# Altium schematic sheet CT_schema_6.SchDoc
size 371 x 245 mm
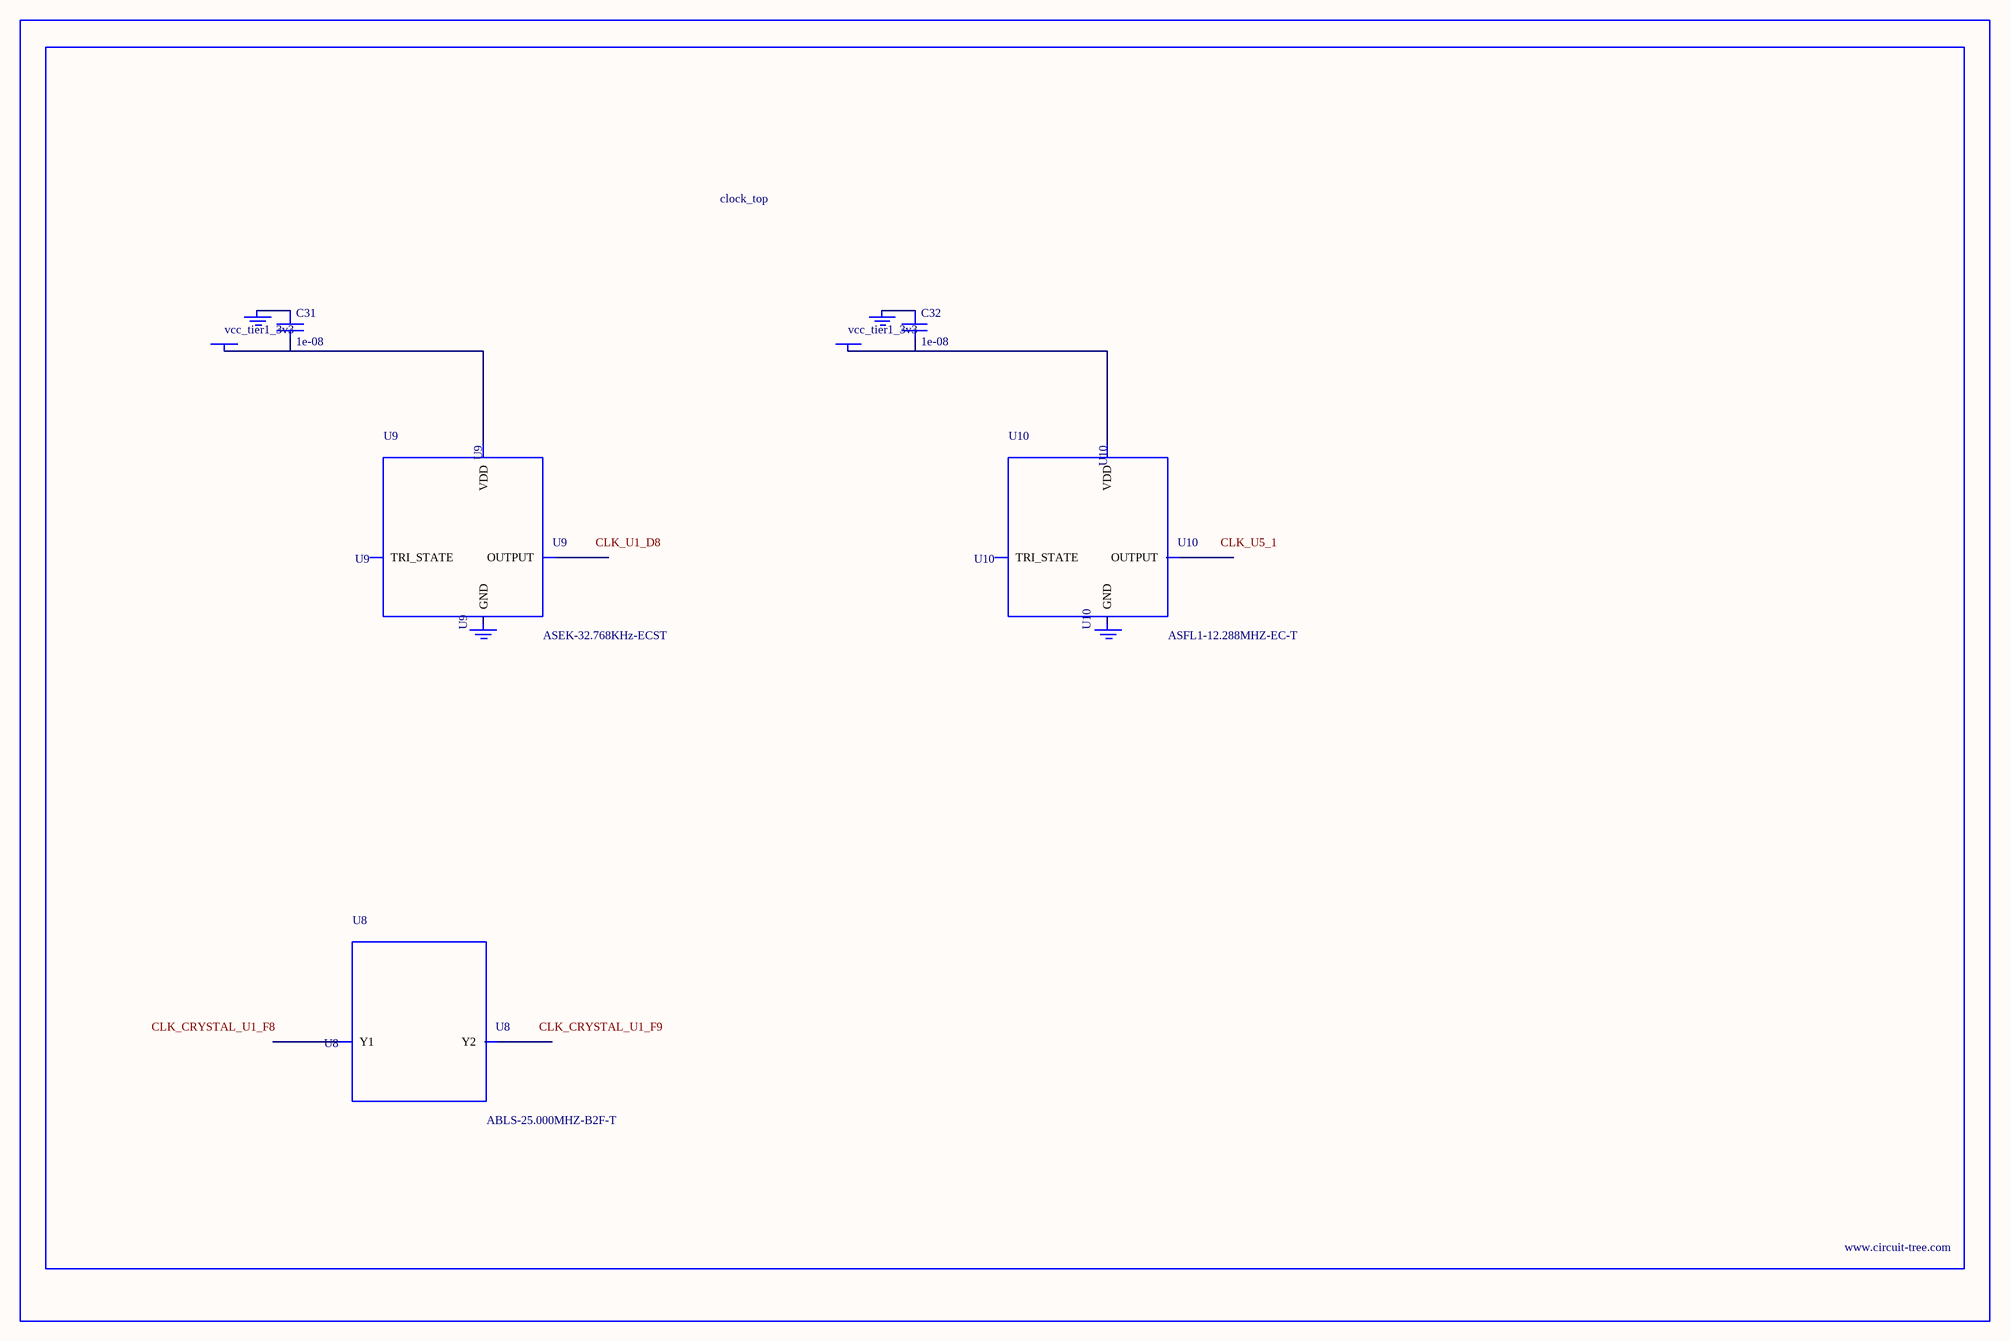
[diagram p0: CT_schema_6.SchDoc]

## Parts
BORDER5  (no value)
C31  1e-08  [C0402]
C32  1e-08  [C0402]
GND_INSTANCE_5_0  (no value)
GND_INSTANCE_5_1  (no value)
GND_INSTANCE_5_2  (no value)
GND_INSTANCE_5_3  (no value)
POWER_INSTANCE_5_0  vcc_tier1_3v3
POWER_INSTANCE_5_1  vcc_tier1_3v3
U8  ABLS-25.000MHZ-B2F-T  [ABLS-25.000MHZ-B2F-T]
U9  ASEK-32.768KHz-ECST  [ASEK]
U10  ASFL1-12.288MHZ-EC-T  [ASFL1]

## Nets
NetC31_1: C31.1 GND_INSTANCE_5_0.0(GND)
NetC31_2: C31.2 POWER_INSTANCE_5_0.0(PWR) U9.4(VDD)
NetC32_1: C32.1 GND_INSTANCE_5_2.0(GND)
NetC32_2: C32.2 POWER_INSTANCE_5_1.0(PWR) U10.4(VDD)

Not connected (* = marked no-connect by the designer): GND_INSTANCE_5_1 0(GND); GND_INSTANCE_5_3 0(GND); U8 1(Y1) 2(Y2); U9 1(TRI_STATE) 2(GND) 3(OUTPUT); U10 1(TRI_STATE) 2(GND) 3(OUTPUT)

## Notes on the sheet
- Labels drawn without touching a wire or pin: CLK_CRYSTAL_U1_F8, CLK_CRYSTAL_U1_F9, CLK_U1_D8, CLK_U5_1

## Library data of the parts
BORDER5 = BORDER_PAGE5
C31 C32 = C0402C103K3RAC
GND_INSTANCE_5_0-GND_INSTANCE_5_3 = GND
POWER_INSTANCE_5_0 POWER_INSTANCE_5_1 = PWR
